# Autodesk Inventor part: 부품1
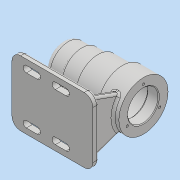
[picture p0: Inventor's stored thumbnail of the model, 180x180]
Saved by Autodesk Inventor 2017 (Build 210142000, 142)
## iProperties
Part Number: 부품1
Material: 일반
Document SubType Name: Modeling
Designer: MRC
Density: 1 g/cm^3
Appearance: 기본값
Mass: 255.647 g
Surface Area: 701.718 cm^2
Volume: 255.647 cm^3
Author: MRC
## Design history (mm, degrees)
sketch "스케치1"
  geometry: L1 (0, 0)-(-112, 0); L2 (0, 0)-(0, 34); L3 (0, 34)-(-32, 34); L4 (-32, 34)-(-32, 30); L5 (-32, 30)-(-66, 30); L6 (-66, 30)-(-66, 27); L7 (-66, 27)-(-88, 27); L8 (-88, 27)-(-88, 25); L9 (-88, 25)-(-112, 25); L10 (-112, 25)-(-112, 0); L11 (-99, 17.5)-(-91.331, 17.5); L12 (-91.331, 17.5)-(-91.331, 17.5); L13 (-91.331, 17.5)-(-81, 17.5); L14 (-81, 17.5)-(-81, 21); L15 (-81, 21)-(-69, 21); L16 (-69, 21)-(-69, 24); L17 (-69, 24)-(-15, 24); L18 (-15, 24)-(-15, 21); L19 (-15, 21)-(0, 21); L20 (-99, 17.5)-(-99, 16); L21 (-99, 16)-(-103, 16); L22 (-103, 16)-(-103, 10.5); L23 (-103, 10.5)-(-106, 10.5); L24 (-106, 10.5)-(-106, 0)
  constraints: 48 end point, 17 perpendicular, 5 point on line, 3 vertical, 1 horizontal
  dimensions: "d0" = 112 distance of L1.start L1.end; "d1" = 68 diameter of L3 L1; "d2" = 60 diameter of L5 L1; "d3" = 54 diameter of L7 L1; "d4" = 50 diameter of L9 L1; "d5" = 24 distance from line of L7.end L10; "d6" = 46 distance from line of L6.end L10; "d7" = 80 distance from line of L3.end L10; "d8" = 42 diameter of L19 L1; "d9" = 48 diameter of L17 L1; "d10" = 35 diameter of L13 L1; "d11" = 32 diameter of L20.end L1; "d12" = 21 diameter of L23 L1; "d13" = 18 distance between parallel lines of L20 L14; "d14" = 12 distance between parallel lines of L16 L14; "d15" = 54 distance from line of L18 L16.end; "d16" = 15 distance between parallel lines of L2 L18; "d17" = 3 distance of L22.end L23.end; "d18" = 4 distance of L20.end L21.end
revolve "회전1" stored, may be unused: angle "d19" = 90 deg
fillet "모깎기1" dims "d20" = 0.3
fillet "모깎기2" dims "d21" = 3
chamfer "모따기1" distance "d22" = 1; stored, may be unused: second distance "d23" = 2, angle "d24" = 45 deg
fillet "모깎기3" dims "d25" = 8
node "작업 평면1"
sketch "스케치2"
  geometry: L1 (112, 45)-(0, 45); L2 (0, 45)-(0, -45); L3 (0, -45)-(112, -45); L4 (112, -45)-(112, 45); L5 (112, 45)-(0, -45); L6 (0, 45)-(112, -45); L7 (0, 34)-(0, -34) reference; 3 further points
  constraints: 12 end point, 4 midpoint, 2 parallel, 1 horizontal, 1 perpendicular
  dimensions: "d27" = 112 distance of L3.end L2.end; "d28" = 90 distance of L2.end L1.end
extrude "돌출1" join sketch "스케치2" distance "d29" = 8; taper "d30" = 0 deg
fillet "모깎기4" dims "d31" = 12
sketch "스케치3"
  geometry: L1 (-112, -33)-(-112, 33) reference; L2 (-77, 33)-(-92, 33); L3 (-77, 37.5)-(-92, 37.5); L4 (-92, 28.5)-(-77, 28.5); L5 (-52, 28.5)-(-37, 28.5); L6 (-37, 33)-(-52, 33); L7 (-37, 37.5)-(-52, 37.5); A1 r 4.5 centre (-77, 33) between (-77, 28.5) and (-77, 37.5); A2 r 4.5 centre (-92, 33) between (-92, 37.5) and (-92, 28.5); A3 r 4.5 centre (-37, 33) between (-37, 28.5) and (-37, 37.5); A4 r 4.5 centre (-52, 33) between (-52, 37.5) and (-52, 28.5); 3 further points
  constraints: 16 end point, 8 point on circle, 8 tangent, 4 centre point, 2 horizontal, 2 midpoint, 2 parallel, 1 horizontal alignment
  dimensions: "d32" = 33 distance from line of point (0, 0) L2; "d33" = 9 distance between parallel lines of L3 L4; "d34" = 15 distance of L3.start L3.end; "d35" = 20 distance from line of L3.end L1; "d38" = 9 distance between parallel lines of L7 L5; "d39" = 15 distance of L7.start L7.end; "d40" = 25 distance of L7.end L3.start
extrude "돌출2" cut sketch "스케치3" distance "d36" = 8; taper "d37" = 0 deg
extrude "돌출3" cut sketch "스케치3" distance "d41" = 8; taper "d42" = 0 deg
node "작업 평면2"
fillet "모깎기5" dims "d45" = 3
node "작업 평면3"
sketch "스케치5"
  geometry: L1 (9.591, 45.342)-(-4, 8); L2 (56.409, 45.342)-(70, 8); L3 (-4.5, 8)-(4.5, 8) reference; L4 (66, 8)-(0, 8) reference; L5 (78, 0)-(78, 8) reference; L6 (-12, 8)-(-12, 0) reference; L7 (-4, 8)-(70, 8); L8 (-4.5, 8)-(4.5, 8) reference; A1 r 34 centre (33, 70) between (9.591, 45.342) and (56.409, 45.342) reference; 1 further point
  constraints: 6 end point, 2 point on circle, 2 point on line, 1 collinear
  dimensions: "d47" = 8 distance from line of L2.end L5; "d48" = 8 distance from line of L1.end L6; "d49" = 110 deg angle of L3 L1; "d50" = 110 deg angle of L4 L2
extrude "돌출4" join sketch "스케치5" distance "d51" = 8; taper "d52" = 0 deg
sketch "스케치6"
  geometry: L1 (-80.101, -43.716)-(-85, -62); L2 (-100, -62)-(-12, -62) reference; L3 (-8, -24.658)-(-8, -62) reference; 1 further point
  constraints: 2 end point, 1 point on line
  dimensions: "d53" = 105 deg angle of L1 L2; "d54" = 77 distance from line of L3 L1.end
feature "리브1" sketch "스케치6" dims "d55" = 1, "d56" = 8, "d57" = 0, "d58" = 0, "d59" = 1, "d60" = 1
fillet "모깎기6" dims "d61" = 3
fillet "모깎기7" dims "d62" = 3
fillet "모깎기8" dims "d63" = 3
sketch "스케치7"
  geometry: C1 r 22 at (0, 0) reference; 1 further point
  constraints: 1 horizontal alignment
  dimensions: "d64" = 26 distance of point (-26, 0) C1.centre
hole "구멍1" sketch "스케치7" at (-26, 0) diameter "d65" = 3.242; stored, may be unused: countersink angle "d69" = 90 deg, drill point angle "d71" = 118 deg; dims "d66" = 8, "d67" = 4, "d68" = 2, "d70" = 11
sketch "스케치8"
  geometry: L1 (-112, 33)-(-112, -33) reference; 2 further points
  constraints: 1 horizontal alignment, 1 other
  dimensions: "d75" = 12 distance from line of point (-100, 0) L1
feature "엠보싱1" sketch "스케치8" dims "d0" = 112, "d1" = 68, "d2" = 60, "d3" = 54, "d4" = 50, "d5" = 24, "d6" = 46, "d7" = 80, "d8" = 42, "d9" = 48, "d10" = 35, "d11" = 32, "d12" = 21, "d13" = 18, "d14" = 12, "d15" = 54, "d16" = 15, "d17" = 3, "d18" = 4, "d76" = 0.5, "d77" = 0
fillet "모깎기9" dims "d78" = 0.3
node "솔리드1"
mirror "미러1"
pattern_circular "원형 패턴1" dims angle "d73" = 360 deg
other parameters: "d46" = -8
